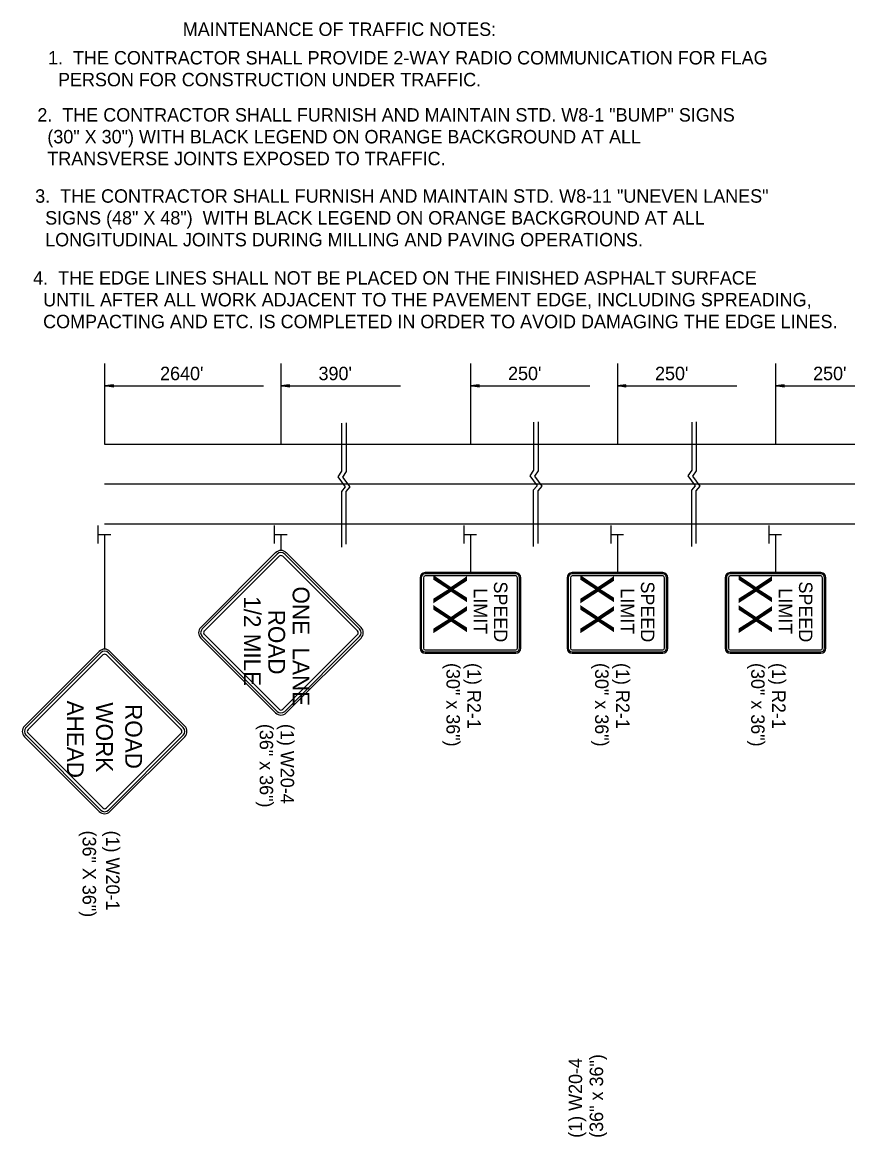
# Model space of a CAD drawing. Extents: x 1927831 to 1930787, y 596452 to 597699.
# Drawn here: x 1927871.5 to 1928240.2, y 597196.1 to 597694.1 of the extents above; entities that cross this region are included whole.
import ezdxf

# ---------------------------------------------------------------- set-up
doc = ezdxf.new("R2010")
doc.units = 0
for name, color, linetype in [('Default', 7, 'Continuous'), ('P_TC_Signs_Permanent', 7, 'Continuous'), ('P_TC_Signs_Temporary', 7, 'Continuous'), ('R_Annotation', 7, 'Continuous')]:
    doc.layers.add(name, color=color, linetype=linetype)

msp = doc.modelspace()

# ---------------------------------------------------------------- linework, layer by layer
at = {"layer": 'Default'}
for p, q in [((1927908.3, 597541.61), (1927908.3, 597505.58)), ((1927987.03, 597541.61), (1927987.03, 597505.56)), ((1928071.69, 597541.61), (1928071.69, 597505.58)), ((1928137.35, 597541.61), (1928137.35, 597505.58)), ((1928207.95, 597541.61), (1928207.95, 597505.58)), ((1927912.18, 597532.14), (1927908.34, 597531.57)), ((1927912.18, 597530.99), (1927908.34, 597531.57)), ((1927908.34, 597531.57), (1927979.22, 597531.57)), ((1927912.18, 597532.05), (1927908.98, 597531.57)), ((1927912.18, 597531.09), (1927908.98, 597531.57)), ((1927912.18, 597531.95), (1927909.64, 597531.57)), ((1927912.18, 597531.18), (1927909.64, 597531.57)), ((1927912.18, 597531.85), (1927910.28, 597531.57)), ((1927912.18, 597531.28), (1927910.28, 597531.57)), ((1927912.18, 597531.75), (1927910.93, 597531.57)), ((1927912.18, 597531.38), (1927910.93, 597531.57)), ((1927912.18, 597531.66), (1927911.57, 597531.57)), ((1927912.18, 597531.48), (1927911.57, 597531.57)), ((1927912.18, 597530.99), (1927912.18, 597532.14)), ((1927990.87, 597532.14), (1927987.03, 597531.57)), ((1927990.87, 597530.99), (1927987.03, 597531.57)), ((1927987.03, 597531.57), (1928040.44, 597531.57)), ((1927990.87, 597532.05), (1927987.67, 597531.57)), ((1927990.87, 597531.09), (1927987.67, 597531.57)), ((1927990.87, 597531.95), (1927988.33, 597531.57)), ((1927990.87, 597531.18), (1927988.33, 597531.57)), ((1927990.87, 597531.85), (1927988.97, 597531.57)), ((1927990.87, 597531.28), (1927988.97, 597531.57)), ((1927990.87, 597531.75), (1927989.62, 597531.57)), ((1927990.87, 597531.38), (1927989.62, 597531.57)), ((1927990.87, 597531.66), (1927990.26, 597531.57)), ((1927990.87, 597531.48), (1927990.26, 597531.57)), ((1927990.87, 597530.99), (1927990.87, 597532.14)), ((1928075.53, 597532.14), (1928071.69, 597531.57)), ((1928071.69, 597531.57), (1928125.09, 597531.57)), ((1928075.53, 597530.99), (1928071.69, 597531.57)), ((1928075.53, 597532.05), (1928072.33, 597531.57)), ((1928075.53, 597531.09), (1928072.33, 597531.57)), ((1928075.53, 597531.95), (1928072.99, 597531.57)), ((1928075.53, 597531.18), (1928072.99, 597531.57)), ((1928075.53, 597531.85), (1928073.63, 597531.57)), ((1928075.53, 597531.28), (1928073.63, 597531.57)), ((1928075.53, 597531.75), (1928074.28, 597531.57)), ((1928075.53, 597531.38), (1928074.28, 597531.57)), ((1928075.53, 597531.66), (1928074.92, 597531.57)), ((1928075.53, 597531.48), (1928074.92, 597531.57)), ((1928075.53, 597530.99), (1928075.53, 597532.14)), ((1928141.18, 597532.14), (1928137.35, 597531.57)), ((1928137.35, 597531.57), (1928190.75, 597531.57)), ((1928141.18, 597530.99), (1928137.35, 597531.57)), ((1928141.18, 597532.05), (1928137.99, 597531.57)), ((1928141.18, 597531.09), (1928137.99, 597531.57)), ((1928141.18, 597531.95), (1928138.65, 597531.57)), ((1928141.18, 597531.18), (1928138.65, 597531.57)), ((1928141.18, 597531.85), (1928139.29, 597531.57)), ((1928141.18, 597531.28), (1928139.29, 597531.57)), ((1928141.18, 597531.75), (1928139.94, 597531.57)), ((1928141.18, 597531.38), (1928139.94, 597531.57)), ((1928141.18, 597531.66), (1928140.58, 597531.57)), ((1928141.18, 597531.48), (1928140.58, 597531.57)), ((1928141.18, 597530.99), (1928141.18, 597532.14)), ((1928211.79, 597532.14), (1928207.95, 597531.57)), ((1928207.95, 597531.57), (1928261.36, 597531.59)), ((1928211.79, 597530.99), (1928207.95, 597531.57)), ((1928211.79, 597532.05), (1928208.6, 597531.57)), ((1928211.79, 597531.09), (1928208.6, 597531.57)), ((1928211.79, 597531.95), (1928209.26, 597531.57)), ((1928211.79, 597531.18), (1928209.26, 597531.57)), ((1928211.79, 597531.85), (1928209.89, 597531.57)), ((1928211.79, 597531.28), (1928209.89, 597531.57)), ((1928211.79, 597531.75), (1928210.55, 597531.57)), ((1928211.79, 597531.38), (1928210.55, 597531.57)), ((1928211.79, 597531.66), (1928211.19, 597531.57)), ((1928211.79, 597531.48), (1928211.19, 597531.57)), ((1928211.79, 597530.99), (1928211.79, 597532.14)), ((1927908.3, 597505.58), (1928044.85, 597505.58)), ((1928044.85, 597505.58), (1929173.7, 597505.58)), ((1927908.3, 597487.79), (1929173.7, 597487.79)), ((1927905.45, 597461.2), (1927905.45, 597469.2)), ((1927908.3, 597470), (1928044.85, 597470)), ((1927984.18, 597461.2), (1927984.18, 597469.2)), ((1928044.85, 597470), (1929173.7, 597470)), ((1928068.84, 597461.2), (1928068.84, 597469.2)), ((1928134.5, 597461.2), (1928134.5, 597469.2)), ((1928205.1, 597461.2), (1928205.1, 597469.2)), ((1927905.57, 597465.18), (1927911.03, 597465.18)), ((1927984.3, 597465.18), (1927989.77, 597465.18)), ((1928068.96, 597465.18), (1928074.42, 597465.18)), ((1928134.61, 597465.18), (1928140.08, 597465.18)), ((1928205.22, 597465.18), (1928210.69, 597465.18))]:
    msp.add_line(p, q, dxfattribs=at)
for points in [[(1928014.17, 597514.95), (1928014.17, 597493.43), (1928012.5, 597490.96), (1928015.74, 597486.53), (1928014.04, 597484.48), (1928014.03, 597459.46)], [(1928016.21, 597515.15), (1928016.21, 597493.34), (1928014.55, 597490.87), (1928017.79, 597486.44), (1928016.08, 597484.4), (1928016.08, 597460.9)], [(1928099.91, 597515.4), (1928099.91, 597493.87), (1928098.25, 597491.4), (1928101.48, 597486.97), (1928099.78, 597484.93), (1928099.77, 597459.9)], [(1928101.95, 597515.49), (1928101.95, 597493.69), (1928100.29, 597491.21), (1928103.53, 597486.78), (1928101.82, 597484.74), (1928101.82, 597461.24)], [(1928170.52, 597515.4), (1928170.52, 597493.87), (1928168.85, 597491.4), (1928172.09, 597486.97), (1928170.39, 597484.93), (1928170.38, 597459.9)], [(1928172.56, 597515.49), (1928172.56, 597493.69), (1928170.9, 597491.21), (1928174.14, 597486.78), (1928172.43, 597484.74), (1928172.43, 597461.24)]]:
    msp.add_lwpolyline(points, dxfattribs=at)
at = {"layer": 'P_TC_Signs_Permanent'}
for p, q in [((1928049.19, 597445.9), (1928049.19, 597414.4)), ((1928049.75, 597445.9), (1928049.75, 597414.4)), ((1928050.69, 597445.9), (1928050.69, 597414.4)), ((1928091.94, 597448.15), (1928051.44, 597448.15)), ((1928091.94, 597447.59), (1928051.44, 597447.59)), ((1928091.94, 597446.65), (1928051.44, 597446.65)), ((1928092.69, 597414.4), (1928092.69, 597445.9)), ((1928093.63, 597414.4), (1928093.63, 597445.9)), ((1928094.19, 597414.4), (1928094.19, 597445.9)), ((1928114.85, 597445.9), (1928114.85, 597414.4)), ((1928115.41, 597445.9), (1928115.41, 597414.4)), ((1928116.35, 597445.9), (1928116.35, 597414.4)), ((1928157.6, 597448.15), (1928117.1, 597448.15)), ((1928157.6, 597447.59), (1928117.1, 597447.59)), ((1928157.6, 597446.65), (1928117.1, 597446.65)), ((1928158.35, 597414.4), (1928158.35, 597445.9)), ((1928159.28, 597414.4), (1928159.28, 597445.9)), ((1928159.85, 597414.4), (1928159.85, 597445.9)), ((1928185.45, 597445.9), (1928185.45, 597414.4)), ((1928186.02, 597445.9), (1928186.02, 597414.4)), ((1928186.95, 597445.9), (1928186.95, 597414.4)), ((1928228.2, 597448.15), (1928187.7, 597448.15)), ((1928228.2, 597447.59), (1928187.7, 597447.59)), ((1928228.2, 597446.65), (1928187.7, 597446.65)), ((1928228.95, 597414.4), (1928228.95, 597445.9)), ((1928229.89, 597414.4), (1928229.89, 597445.9)), ((1928230.45, 597414.4), (1928230.45, 597445.9)), ((1928051.44, 597413.65), (1928091.94, 597413.65)), ((1928117.1, 597413.65), (1928157.6, 597413.65)), ((1928187.7, 597413.65), (1928228.2, 597413.65)), ((1928051.44, 597412.71), (1928091.94, 597412.71)), ((1928051.44, 597412.15), (1928091.94, 597412.15)), ((1928117.1, 597412.71), (1928157.6, 597412.71)), ((1928117.1, 597412.15), (1928157.6, 597412.15)), ((1928187.7, 597412.71), (1928228.2, 597412.71)), ((1928187.7, 597412.15), (1928228.2, 597412.15))]:
    msp.add_line(p, q, dxfattribs=at)
for centre, radius, start, end in [((1928051.44, 597445.9), 2.25, 90, 180), ((1928051.44, 597445.9), 1.69, 90, 180), ((1928051.44, 597445.9), 0.75, 90, 180), ((1928091.94, 597445.9), 2.25, 360, 90), ((1928091.94, 597445.9), 1.69, 360, 90), ((1928091.94, 597445.9), 0.75, 360, 90), ((1928117.1, 597445.9), 2.25, 90, 180), ((1928117.1, 597445.9), 1.69, 90, 180), ((1928117.1, 597445.9), 0.75, 90, 180), ((1928157.6, 597445.9), 2.25, 360, 90), ((1928157.6, 597445.9), 1.69, 360, 90), ((1928157.6, 597445.9), 0.75, 360, 90), ((1928187.7, 597445.9), 2.25, 90, 180), ((1928187.7, 597445.9), 1.69, 90, 180), ((1928187.7, 597445.9), 0.75, 90, 180), ((1928228.2, 597445.9), 2.25, 360, 90), ((1928228.2, 597445.9), 1.69, 360, 90), ((1928228.2, 597445.9), 0.75, 360, 90), ((1928051.44, 597414.4), 2.25, 180, 270), ((1928051.44, 597414.4), 1.69, 180, 270), ((1928051.44, 597414.4), 0.75, 180, 270), ((1928091.94, 597414.4), 2.25, 270, 360), ((1928091.94, 597414.4), 1.69, 270, 360), ((1928091.94, 597414.4), 0.75, 270, 360), ((1928117.1, 597414.4), 2.25, 180, 270), ((1928117.1, 597414.4), 1.69, 180, 270), ((1928117.1, 597414.4), 0.75, 180, 270), ((1928157.6, 597414.4), 2.25, 270, 360), ((1928157.6, 597414.4), 1.69, 270, 360), ((1928157.6, 597414.4), 0.75, 270, 360), ((1928187.7, 597414.4), 2.25, 180, 270), ((1928187.7, 597414.4), 1.69, 180, 270), ((1928187.7, 597414.4), 0.75, 180, 270), ((1928228.2, 597414.4), 2.25, 270, 360), ((1928228.2, 597414.4), 1.69, 270, 360), ((1928228.2, 597414.4), 0.75, 270, 360)]:
    msp.add_arc(centre, radius, start, end, dxfattribs=at)
at = {"layer": 'P_TC_Signs_Temporary'}
for p, q in [((1927951.24, 597423.67), (1927984.65, 597457.08)), ((1927951.9, 597423), (1927985.31, 597456.42)), ((1927952.83, 597422.08), (1927986.24, 597455.49)), ((1927987.83, 597455.49), (1928021.24, 597422.08)), ((1927988.76, 597456.42), (1928022.17, 597423)), ((1927989.42, 597457.08), (1928022.83, 597423.67)), ((1927984.65, 597385.48), (1927951.24, 597418.89)), ((1927985.31, 597386.15), (1927951.9, 597419.56)), ((1927986.24, 597387.07), (1927952.83, 597420.49)), ((1928021.24, 597420.49), (1927987.83, 597387.07)), ((1928022.17, 597419.56), (1927988.76, 597386.15)), ((1928022.83, 597418.89), (1927989.42, 597385.48)), ((1927872.5, 597379.57), (1927905.91, 597412.98)), ((1927873.17, 597378.91), (1927906.58, 597412.32)), ((1927874.09, 597377.98), (1927907.5, 597411.39)), ((1927909.1, 597411.39), (1927942.51, 597377.98)), ((1927910.02, 597412.32), (1927943.43, 597378.91)), ((1927910.69, 597412.98), (1927944.1, 597379.57)), ((1927905.91, 597341.39), (1927872.5, 597374.8)), ((1927906.58, 597342.05), (1927873.17, 597375.46)), ((1927907.5, 597342.98), (1927874.09, 597376.39)), ((1927942.51, 597376.39), (1927909.1, 597342.98)), ((1927943.43, 597375.46), (1927910.02, 597342.05)), ((1927944.1, 597374.8), (1927910.69, 597341.39))]:
    msp.add_line(p, q, dxfattribs=at)
for centre, radius, start, end in [((1927987.03, 597454.69), 3.37, 45, 135), ((1927987.03, 597454.69), 2.44, 45, 135), ((1927987.03, 597454.69), 1.12, 45, 135), ((1927953.62, 597421.28), 3.37, 135, 225), ((1928020.44, 597421.28), 3.37, 315, 45), ((1927953.62, 597421.28), 2.44, 135, 225), ((1927953.62, 597421.28), 1.13, 135, 225), ((1928020.44, 597421.28), 1.13, 315, 45), ((1928020.44, 597421.28), 2.44, 315, 45), ((1927908.3, 597410.59), 3.37, 45, 135), ((1927908.3, 597410.59), 2.44, 45, 135), ((1927908.3, 597410.59), 1.12, 45, 135), ((1927987.03, 597387.87), 3.37, 225, 315), ((1927987.03, 597387.87), 2.44, 225, 315), ((1927987.03, 597387.87), 1.12, 225, 315), ((1927874.89, 597377.18), 3.37, 135, 225), ((1927874.89, 597377.18), 2.44, 135, 225), ((1927941.71, 597377.18), 2.44, 315, 45), ((1927941.71, 597377.18), 3.37, 315, 45), ((1927874.89, 597377.18), 1.13, 135, 225), ((1927941.71, 597377.18), 1.13, 315, 45), ((1927908.3, 597343.77), 3.38, 225, 315), ((1927908.3, 597343.77), 2.44, 225, 315), ((1927908.3, 597343.77), 1.12, 225, 315)]:
    msp.add_arc(centre, radius, start, end, dxfattribs=at)
at = {"layer": 'R_Annotation'}
for p, q in [((1927908.3, 597465.18), (1927908.3, 597413.97)), ((1927987.03, 597465.18), (1927987.03, 597458.07)), ((1928071.69, 597465.18), (1928071.69, 597448.15)), ((1928137.35, 597465.18), (1928137.35, 597448.15)), ((1928207.95, 597465.18), (1928207.95, 597448.15))]:
    msp.add_line(p, q, dxfattribs=at)

# ---------------------------------------------------------------- texts
at = {"layer": 'Default'}
for s, p in [("2640'", (1927933.06, 597534.16)), ("390'", (1928003.83, 597534.16)), ("250'", (1928088.49, 597534.18)), ("250'", (1928154.15, 597534.16)), ("250'", (1928224.76, 597534.16))]:
    msp.add_text(s, height=6, rotation=360, dxfattribs=at).set_placement(p)
at = {"layer": 'P_TC_Signs_Permanent'}
for s, height, p in [('XX', 15, (1928055.19, 597447.45)), ('SPEED', 6, (1928082.19, 597444.22)), ('XX', 15, (1928120.85, 597447.45)), ('SPEED', 6, (1928147.85, 597444.22)), ('XX', 15, (1928191.45, 597447.45)), ('SPEED', 6, (1928218.45, 597444.22)), ('LIMIT', 6, (1928073.19, 597441.13)), ('LIMIT', 6, (1928138.85, 597441.13)), ('LIMIT', 6, (1928209.45, 597441.13))]:
    msp.add_text(s, height=height, rotation=270, dxfattribs=at).set_placement(p)
at = {"layer": 'P_TC_Signs_Temporary'}
for s, p in [('ONE  LANE', (1927992.28, 597441.98)), ('1/2 MILE', (1927970.53, 597437.6)), ('ROAD', (1927981.41, 597431.59)), (' AHEAD ', (1927891.47, 597393.72)), ('WORK', (1927904.49, 597390.17)), (' ROAD ', (1927917.51, 597392.2))]:
    msp.add_text(s, height=7.5, rotation=270, dxfattribs=at).set_placement(p)
at = {"layer": 'R_Annotation'}
for s, height, rotation, p in [('MAINTENANCE OF TRAFFIC NOTES:', 6, 360, (1927943.21, 597688)), ('1.  THE CONTRACTOR SHALL PROVIDE 2-WAY RADIO COMMUNICATION FOR FLAG ', 6, 360, (1927883.02, 597675.24)), ('  PERSON FOR CONSTRUCTION UNDER TRAFFIC.', 6, 360, (1927883.02, 597665.49)), ('2.  THE CONTRACTOR SHALL FURNISH AND MAINTAIN STD. W8-1 "BUMP" SIGNS', 6, 360, (1927878.25, 597649.72)), ('  (30" X 30") WITH BLACK LEGEND ON ORANGE BACKGROUND AT ALL ', 6, 360, (1927878.25, 597639.97)), ('  TRANSVERSE JOINTS EXPOSED TO TRAFFIC.', 6, 360, (1927878.25, 597630.22)), ('3.  THE CONTRACTOR SHALL FURNISH AND MAINTAIN STD. W8-11 "UNEVEN LANES" ', 6, 360, (1927877.27, 597613.46)), ('  SIGNS (48" X 48")  WITH BLACK LEGEND ON ORANGE BACKGROUND AT ALL ', 6, 360, (1927877.27, 597603.71)), ('  LONGITUDINAL JOINTS DURING MILLING AND PAVING OPERATIONS.', 6, 360, (1927877.27, 597593.96)), ('4.  THE EDGE LINES SHALL NOT BE PLACED ON THE FINISHED ASPHALT SURFACE', 6, 360, (1927876.36, 597576.87)), ('  UNTIL AFTER ALL WORK ADJACENT TO THE PAVEMENT EDGE, INCLUDING SPREADING,', 6, 360, (1927876.36, 597567.12)), ('  COMPACTING AND ETC. IS COMPLETED IN ORDER TO AVOID DAMAGING THE EDGE LINES.', 6, 360, (1927876.36, 597557.37)), ('(30" x 36")', 5.9996, 270, (1928060.98, 597407.77)), ('(1) R2-1', 6, 270, (1928070.34, 597407.77)), ('(30" x 36")', 5.9996, 270, (1928127.39, 597407.77)), ('(1) R2-1', 6, 270, (1928136.75, 597407.77)), ('(30" x 36")', 5.9996, 270, (1928197.1, 597407.77)), ('(1) R2-1', 6, 270, (1928206.47, 597407.77)), ('(36" x 36")', 5.9996, 270, (1927977.56, 597380.55)), ('(1) W20-4', 6, 270, (1927986.92, 597380.55)), ('(36" X 36")', 6, 270, (1927898.46, 597332.87)), ('(1) W20-1', 6, 270, (1927908.94, 597332.87)), ('(1) W20-4', 6, 90, (1928121.59, 597195.58)), ('(36" x 36")', 5.9996, 90, (1928130.95, 597195.58))]:
    msp.add_text(s, height=height, rotation=rotation, dxfattribs=at).set_placement(p)

doc.saveas('drawing.dxf')
